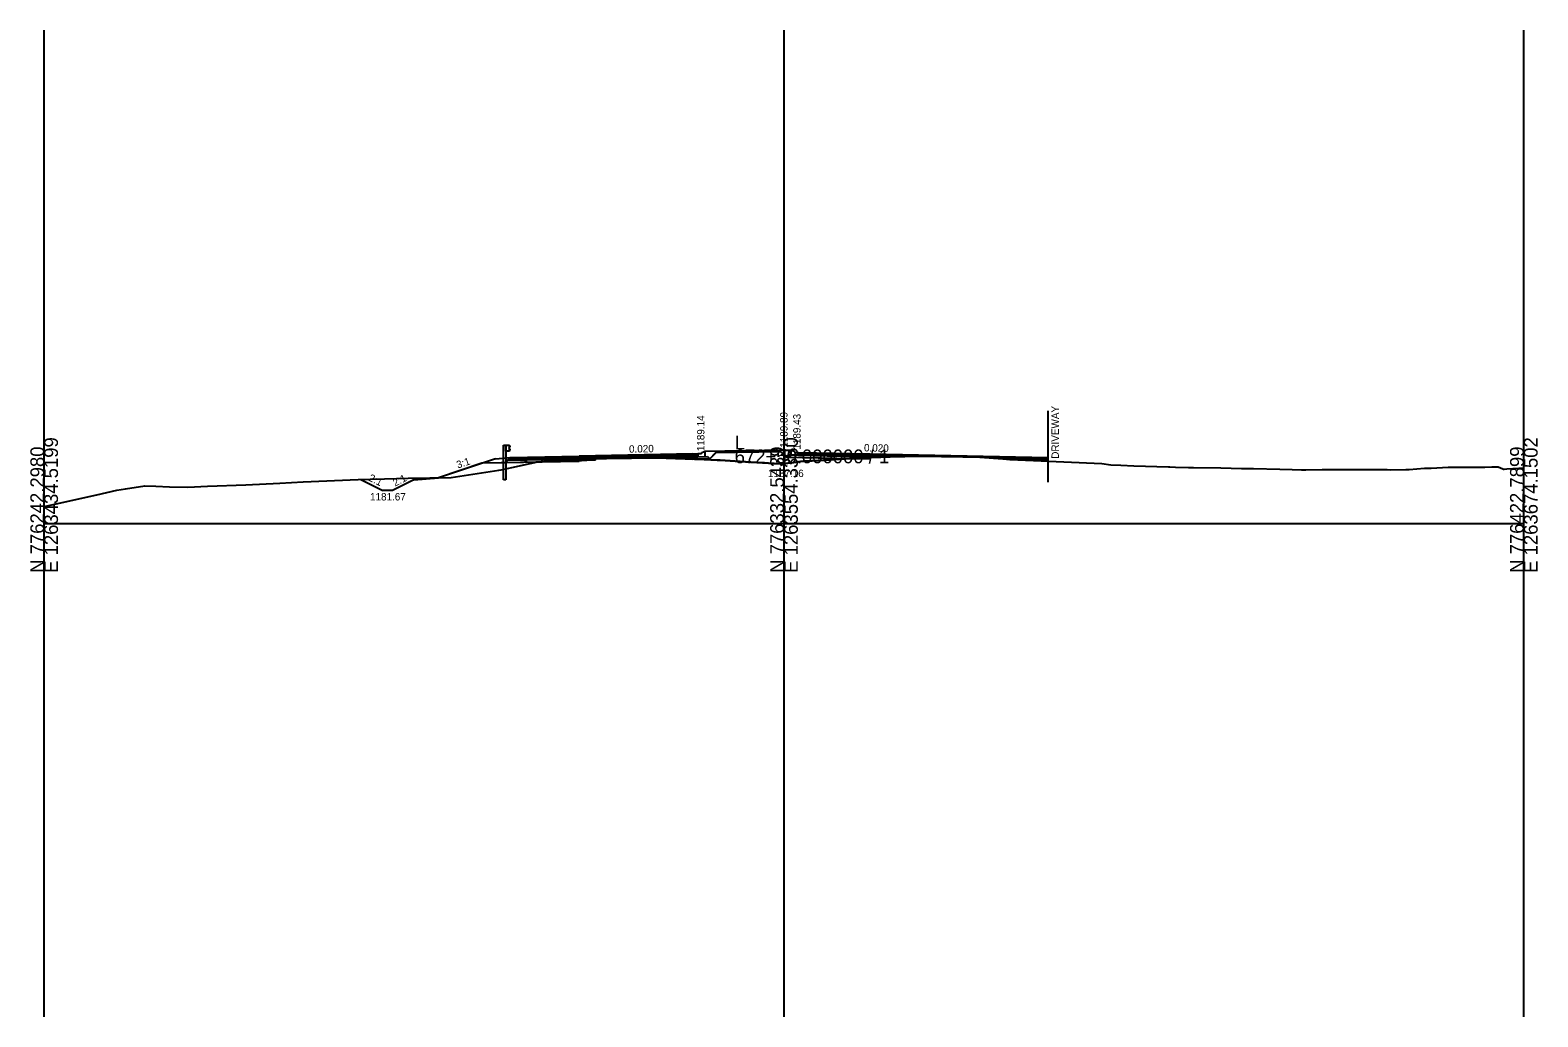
# Model space of a CAD drawing. Extents: x -41 to 1262860, y -100 to 777489.
# Drawn here: x 497.2 to 802.8, y -100 to 100 of the extents above; entities that cross this region are included whole.
import ezdxf

# ---------------------------------------------------------------- set-up
doc = ezdxf.new("R2010")
doc.units = 0
for name, color, linetype in [('Exist Cross Section Cell', 7, 'Continuous'), ('Exist XS Center Line Elevation Label', 7, 'Continuous'), ('Exist XS Ground Line', 7, 'Continuous'), ('Prop CMT Guardrail Graphics', 7, 'Continuous'), ('Prop CMT Pvmt Course 1', 7, 'Continuous'), ('Prop CMT Pvmt Course 4', 7, 'Continuous'), ('Prop CMT Pvmt Surface', 7, 'Continuous'), ('Prop CMT Shear Line', 7, 'Continuous'), ('Prop CMT Shld Paved Course 1', 7, 'Continuous'), ('Prop CMT Shld Paved Course 2', 7, 'Continuous'), ('Prop CMT Shld Paved Course 4', 7, 'Continuous'), ('Prop CMT Subgrade Earthwork', 7, 'Continuous'), ('Prop Conc Curb and Gutter', 7, 'Continuous'), ('Prop Conc Island Cover', 7, 'Continuous'), ('Prop XS Ditch Standard Text', 7, 'Continuous'), ('Prop XS Earthwork Shape', 7, 'Continuous'), ('Prop XS Elevation Labels', 7, 'Continuous'), ('Prop XS Exc Vertical Line 1', 7, 'Continuous'), ('Prop XS Exc Vertical Line 2', 7, 'Continuous'), ('Prop XS Exc Vertical Line 3', 7, 'Continuous'), ('Prop XS Finish Grade', 7, 'Continuous'), ('Prop XS Hydro Elevations', 7, 'Continuous'), ('Prop XS SE Text', 7, 'Continuous'), ('Prop XS Side Slope Text', 7, 'Continuous'), ('Scratch_Level_4', 7, 'Continuous'), ('Scratch_Level_6', 7, 'Continuous')]:
    doc.layers.add(name, color=color, linetype=linetype)

msp = doc.modelspace()

# ---------------------------------------------------------------- linework, layer by layer
at = {"layer": 'Exist Cross Section Cell'}
for p, q in [((650, 0), (650, 15)), ((500, 0), (650, 0)), ((650, 0), (800, 0))]:
    msp.add_line(p, q, dxfattribs=at)
at = {"layer": 'Exist XS Ground Line'}
msp.add_lwpolyline([(500, 3.44), (502.46, 4.01), (510.65, 5.78), (514.74, 6.73), (516.46, 7.06), (520.41, 7.65), (522.67, 7.59), (525.43, 7.43), (529.13, 7.38), (533.11, 7.6), (540.86, 7.86), (547.81, 8.15), (552.5, 8.42), (563.68, 8.92), (566.09, 9.01), (569.03, 9.08), (573.8, 9.17), (582.54, 9.32), (592.15, 10.78), (592.64, 10.85), (596.36, 11.69), (600.09, 12.51), (600.77, 12.59), (603.01, 12.87), (604.8, 12.78), (607.77, 12.72), (611.14, 12.92), (611.74, 12.93), (611.86, 13.16), (613.99, 13.2), (624.15, 13.31), (633.79, 12.96), (636.48, 12.86), (637.06, 12.83), (639.11, 12.7), (643.24, 12.43), (643.28, 12.42), (649.25, 12.08), (651.61, 12.33), (653.33, 12.56), (654.08, 12.62), (654.51, 12.65), (659.36, 12.93), (665.76, 13.31), (671.51, 13.51), (677.56, 13.68), (686.23, 13.51), (689.68, 13.45), (694.38, 13.08), (695.8, 12.96), (700.56, 12.78), (714.47, 12.19), (716.29, 11.91), (718.3, 11.82), (720.92, 11.71), (727.94, 11.47), (728.24, 11.46), (729.37, 11.43), (732.02, 11.38), (733.05, 11.36), (738.59, 11.25), (742.77, 11.17), (745.19, 11.14), (750.54, 11.01), (753.05, 10.96), (754.91, 10.89), (755.83, 10.91), (759.12, 10.92), (759.82, 10.93), (768.32, 10.93), (772.29, 10.92), (773.04, 10.91), (776.09, 10.94), (776.72, 10.97), (779.88, 11.22), (781.19, 11.23), (784.63, 11.4), (784.84, 11.4), (785, 11.4), (785.23, 11.4), (785.56, 11.4), (786.13, 11.4), (792.07, 11.45), (793.49, 11.47), (794.81, 11.48), (795.75, 11.06), (795.89, 11), (796.02, 11.01), (796.54, 11.05), (797.74, 11.15), (797.89, 11.17), (800, 11.25)], dxfattribs=at)
at = {"layer": 'Prop CMT Guardrail Graphics'}
for p, q in [((593.11, 15.87), (593.59, 15.87)), ((593.11, 13.37), (593.11, 15.87)), ((593.59, 14.69), (593.59, 15.87)), ((593.59, 15.87), (594.26, 15.87)), ((593.59, 15.87), (593.59, 13.36)), ((594.26, 15.87), (594.26, 14.69)), ((594.26, 15.79), (594.26, 14.77)), ((594.36, 15.77), (594.26, 15.79)), ((594.27, 15.33), (594.5, 15.53)), ((594.27, 15.24), (594.27, 15.33)), ((594.5, 15.67), (594.36, 15.77)), ((594.5, 15.53), (594.5, 15.67)), ((593.11, 8.86), (593.11, 13.37)), ((594.26, 14.69), (593.59, 14.69)), ((593.59, 13.36), (593.59, 8.86)), ((594.26, 14.77), (594.36, 14.79)), ((594.5, 15.04), (594.27, 15.24)), ((594.36, 14.79), (594.5, 14.89)), ((594.5, 14.89), (594.5, 15.04)), ((593.59, 8.86), (593.11, 8.86))]:
    msp.add_line(p, q, dxfattribs=at)
at = {"layer": 'Prop CMT Pvmt Course 1'}
for p, q in [((631.5, 13.85), (632.5, 13.87)), ((632.5, 13.87), (632.5, 14.12)), ((652.93, 14.41), (652.93, 14.16)), ((652.93, 14.16), (667.5, 13.87))]:
    msp.add_line(p, q, dxfattribs=at)
for points in [[(608.5, 13.64), (608.5, 13.39), (631.5, 13.85), (631.5, 13.85), (631.5, 14.1), (631.5, 14.1), (631.5, 14.1), (608.5, 13.64), (608.5, 13.64)], [(703.5, 13.4), (703.5, 13.15), (703.5, 13.15), (667.5, 13.87), (667.5, 13.87), (667.5, 14.12), (667.5, 14.12), (667.5, 14.12), (703.5, 13.4), (703.5, 13.4), (703.5, 13.4)]]:
    msp.add_lwpolyline(points, dxfattribs=at)
at = {"layer": 'Prop CMT Pvmt Course 4'}
for p in [(593.9, 12.77), (608.5, 12.6)]:
    msp.add_line(p, (593.44, 12.3), dxfattribs=at)
at = {"layer": 'Prop CMT Pvmt Surface'}
for p, q in [((594.5, 13.36), (608.5, 13.64)), ((608.5, 13.64), (631.5, 14.1)), ((631.5, 14.1), (632.5, 14.12)), ((652.93, 14.41), (667.5, 14.12)), ((667.5, 14.12), (703.5, 13.4))]:
    msp.add_line(p, q, dxfattribs=at)
at = {"layer": 'Prop CMT Shear Line'}
msp.add_line((703.5, 22.84), (703.5, 8.4), dxfattribs=at)
at = {"layer": 'Prop CMT Shld Paved Course 1'}
for p, q in [((608.5, 13.39), (594.24, 13.11)), ((594.5, 13.36), (594.24, 13.11)), ((604.5, 13.56), (604.5, 13.56)), ((608.5, 13.64), (608.5, 13.39)), ((608.5, 13.39), (608.5, 13.39))]:
    msp.add_line(p, q, dxfattribs=at)
at = {"layer": 'Prop CMT Shld Paved Course 2'}
for p, q in [((593.9, 12.77), (594.24, 13.11)), ((608.5, 13.06), (593.9, 12.77)), ((603.9, 12.97), (603.9, 12.97)), ((603.9, 12.97), (603.9, 12.97)), ((611.14, 13.45), (608.5, 13.39)), ((608.5, 13.39), (608.5, 13.06)), ((608.5, 13.39), (608.5, 13.39)), ((608.5, 13.39), (608.5, 13.39)), ((608.5, 13.39), (608.5, 13.06)), ((608.5, 13.06), (611.14, 13.11)), ((608.5, 13.06), (608.5, 13.06)), ((608.5, 13.06), (608.5, 13.06)), ((611.74, 13.46), (611.14, 13.45)), ((611.14, 13.45), (611.14, 13.45)), ((611.14, 13.11), (611.74, 13.12)), ((611.14, 13.11), (611.14, 13.11)), ((611.86, 13.46), (611.74, 13.46)), ((611.74, 13.46), (611.74, 13.46)), ((611.74, 13.12), (611.84, 13.13)), ((611.84, 13.13), (611.86, 13.16)), ((611.84, 13.13), (611.84, 13.13)), ((613.99, 13.5), (611.86, 13.46)), ((611.86, 13.16), (613.99, 13.2)), ((624.15, 13.71), (613.99, 13.5)), ((613.99, 13.5), (613.99, 13.5)), ((613.99, 13.2), (617.56, 13.24)), ((613.99, 13.2), (613.99, 13.2)), ((617.56, 13.24), (624.15, 13.37)), ((617.56, 13.24), (617.56, 13.24)), ((617.56, 13.24), (617.56, 13.24)), ((631.5, 13.85), (624.15, 13.71)), ((624.15, 13.71), (624.15, 13.71)), ((624.15, 13.71), (624.15, 13.71)), ((624.15, 13.37), (631.5, 13.52)), ((624.15, 13.37), (624.15, 13.37)), ((624.15, 13.37), (624.15, 13.37)), ((631.5, 13.52), (631.5, 13.85)), ((631.5, 13.85), (631.5, 13.85)), ((631.5, 13.85), (631.5, 13.85)), ((631.5, 13.52), (632.5, 13.54)), ((631.5, 13.52), (631.5, 13.52)), ((632.5, 13.87), (632.5, 13.54)), ((652.93, 13.83), (652.93, 14.16)), ((652.93, 13.83), (667.5, 13.54)), ((667.5, 13.54), (667.5, 13.87)), ((667.5, 13.87), (667.5, 13.87)), ((667.5, 13.87), (671.51, 13.79)), ((670.63, 13.48), (667.5, 13.54)), ((671.51, 13.51), (670.63, 13.48)), ((670.63, 13.48), (670.63, 13.48)), ((671.51, 13.79), (671.51, 13.79)), ((671.51, 13.79), (677.56, 13.67)), ((677.39, 13.67), (671.51, 13.51)), ((671.51, 13.51), (671.51, 13.51)), ((677.56, 13.67), (677.39, 13.67)), ((686.23, 13.5), (677.56, 13.67)), ((677.56, 13.67), (677.56, 13.67)), ((677.56, 13.67), (677.56, 13.67)), ((677.56, 13.67), (686.23, 13.5)), ((689.68, 13.43), (686.23, 13.5)), ((686.23, 13.5), (686.23, 13.5)), ((686.23, 13.5), (686.23, 13.5)), ((686.23, 13.5), (686.23, 13.5)), ((686.23, 13.5), (689.68, 13.43)), ((690.09, 13.42), (689.68, 13.43)), ((689.68, 13.43), (689.68, 13.43)), ((689.68, 13.43), (689.68, 13.43)), ((689.68, 13.43), (689.68, 13.43)), ((689.68, 13.43), (694.38, 13.33)), ((694.38, 13.08), (690.09, 13.42)), ((690.09, 13.42), (690.09, 13.42)), ((690.09, 13.42), (690.09, 13.42)), ((694.38, 13.33), (694.38, 13.33)), ((694.38, 13.33), (694.38, 13.33)), ((694.38, 13.33), (695.8, 13.31)), ((695.63, 12.98), (694.38, 13.08)), ((694.38, 13.08), (694.38, 13.08)), ((694.38, 13.08), (694.38, 13.08)), ((695.8, 12.97), (695.63, 12.98)), ((695.63, 12.98), (695.63, 12.98)), ((695.8, 13.31), (695.8, 13.31)), ((695.8, 13.31), (700.56, 13.21)), ((700.56, 12.88), (695.8, 12.97)), ((695.8, 12.97), (695.8, 12.97)), ((695.8, 12.97), (695.8, 12.97)), ((700.56, 13.21), (703.5, 13.15)), ((700.56, 13.21), (700.56, 13.21)), ((700.56, 13.21), (700.56, 13.21)), ((703.5, 12.82), (700.56, 12.88)), ((700.56, 12.88), (700.56, 12.88)), ((700.56, 12.88), (700.56, 12.88)), ((703.5, 13.15), (703.5, 13.15)), ((703.5, 13.15), (703.5, 13.15)), ((703.5, 13.15), (703.5, 12.82)), ((703.5, 12.82), (703.5, 12.82))]:
    msp.add_line(p, q, dxfattribs=at)
at = {"layer": 'Prop CMT Shld Paved Course 4'}
for p, q in [((597.4, 12.84), (597.9, 12.85)), ((603.9, 12.97), (603.9, 12.97)), ((608.5, 13.06), (608.5, 12.6)), ((611.14, 12.92), (608.5, 12.76)), ((611.74, 12.93), (611.14, 12.92)), ((611.74, 12.93), (611.84, 13.13)), ((617.56, 13.24), (624.15, 13.31)), ((631.5, 13.04), (624.15, 13.31)), ((631.5, 13.06), (631.5, 13.52)), ((631.5, 13.06), (634.95, 13.13)), ((632.5, 13.54), (634.5, 13.58)), ((634.5, 13.58), (634.95, 13.13)), ((650.93, 13.87), (650.48, 13.42)), ((650.48, 13.42), (667.5, 13.08)), ((652.93, 13.83), (650.93, 13.87)), ((667.5, 13.54), (667.5, 13.08)), ((670.63, 13.48), (667.5, 13.37)), ((695.8, 12.96), (695.63, 12.98)), ((695.8, 12.96), (700.56, 12.78)), ((703.5, 12.65), (700.56, 12.78))]:
    msp.add_line(p, q, dxfattribs=at)
at = {"layer": 'Prop CMT Subgrade Earthwork'}
for p, q in [((608.5, 12.6), (588.75, 12.21)), ((608.5, 12.6), (608.5, 12.76)), ((634.95, 13.13), (631.5, 13.06)), ((631.5, 13.06), (631.5, 13.04)), ((634.95, 13.13), (636.44, 14.62)), ((650.48, 13.42), (649.03, 14.87)), ((650.48, 13.42), (667.5, 13.08)), ((667.5, 13.08), (667.5, 13.37))]:
    msp.add_line(p, q, dxfattribs=at)
at = {"layer": 'Prop Conc Curb and Gutter'}
for p, q in [((633.19, 14.14), (632.5, 14.12)), ((632.5, 14.12), (632.5, 13.54)), ((632.5, 13.54), (634, 13.57)), ((633.25, 14.21), (633.25, 14.2)), ((634, 14.57), (633.35, 14.35)), ((634, 13.57), (634, 14.57)), ((634, 13.57), (634, 13.57)), ((651.43, 14.86), (652.08, 14.64)), ((651.43, 13.86), (651.43, 14.86)), ((652.93, 13.83), (651.43, 13.86)), ((652.18, 14.51), (652.18, 14.49)), ((652.24, 14.43), (652.93, 14.41)), ((652.93, 13.83), (652.93, 14.41))]:
    msp.add_line(p, q, dxfattribs=at)
for centre, radius, start, end in [((633.19, 14.2), 0.0625, 271.1458, 360), ((633.4, 14.21), 0.146, 108.435, 180), ((652.03, 14.51), 0.146, 0, 71.565), ((652.24, 14.49), 0.0625, 180, 268.8542)]:
    msp.add_arc(centre, radius, start, end, dxfattribs=at)
at = {"layer": 'Prop Conc Island Cover'}
for p, q in [((650, 14.89), (634, 14.57)), ((634, 14.3), (634, 14.3)), ((650, 14.89), (651.43, 14.86))]:
    msp.add_line(p, q, dxfattribs=at)
at = {"layer": 'Prop XS Earthwork Shape'}
for points in [[(599.71, 12.43), (593.44, 12.3), (588.75, 12.21), (579.96, 9.28), (582.54, 9.32), (592.15, 10.78), (592.64, 10.85), (596.36, 11.69)], [(608.5, 12.6), (599.71, 12.43), (600.09, 12.51), (600.77, 12.59), (603.01, 12.87), (604.8, 12.78), (607.77, 12.72), (608.5, 12.76)], [(636.18, 14.36), (649.27, 14.62), (650.48, 13.42), (663.28, 13.17), (659.36, 12.93), (654.51, 12.65), (654.08, 12.62), (653.33, 12.56), (651.61, 12.33), (649.25, 12.08), (643.28, 12.42), (643.24, 12.43), (639.11, 12.7), (637.06, 12.83), (636.48, 12.86), (633.79, 12.96), (631.5, 13.04), (631.5, 13.06), (634.95, 13.13)], [(667.5, 13.08), (667.5, 13.37), (665.76, 13.31), (663.28, 13.17)]]:
    msp.add_lwpolyline(points, close=True, dxfattribs=at)
at = {"layer": 'Prop XS Exc Vertical Line 1'}
msp.add_line((500, -100), (500, 100), dxfattribs=at)
at = {"layer": 'Prop XS Exc Vertical Line 2'}
msp.add_line((650, -100), (650, 100), dxfattribs=at)
at = {"layer": 'Prop XS Exc Vertical Line 3'}
msp.add_line((800, -100), (800, 100), dxfattribs=at)
at = {"layer": 'Prop XS Finish Grade'}
for p, q in [((591.5, 13.12), (579.96, 9.28)), ((591.5, 13.12), (594.5, 13.36)), ((594.5, 13.36), (593.44, 12.3)), ((574.96, 8.86), (579.96, 9.28)), ((564.17, 8.94), (568.64, 6.7)), ((570.64, 6.7), (568.64, 6.7)), ((574.96, 8.86), (570.64, 6.7))]:
    msp.add_line(p, q, dxfattribs=at)
at = {"layer": 'Scratch_Level_4'}
msp.add_line((800, -100), (800, 100), dxfattribs=at)
at = {"layer": 'Scratch_Level_6'}
msp.add_line((500, -100), (500, 100), dxfattribs=at)

# ---------------------------------------------------------------- texts
at = {"layer": 'Exist Cross Section Cell'}
for s, p in [('N 776242.2980', (500, -10)), ('E 1263434.5199', (502.8, -10)), ('N 776332.5439', (650, -10)), ('E 1263554.3350', (652.8, -10)), ('N 776422.7899', (800, -10)), ('E 1263674.1502', (802.8, -10))]:
    msp.add_text(s, height=2.8, rotation=90, dxfattribs=at).set_placement(p)
for s, p in [('L', (640, 15)), ('672+50.000000 / 1', (640, 12.2))]:
    msp.add_text(s, height=2.8, dxfattribs=at).set_placement(p)
at = {"layer": 'Exist XS Center Line Elevation Label'}
msp.add_text('1187.16', height=1.5, dxfattribs=at).set_placement((646.74, 9.41))
at = {"layer": 'Prop XS Ditch Standard Text'}
msp.add_text('1181.67', height=1.5, dxfattribs=at).set_placement((566.07, 4.67))
at = {"layer": 'Prop XS Elevation Labels'}
for s, p in [('1189.14', (633.87, 14.66)), ('1189.43', (653.36, 14.97))]:
    msp.add_text(s, height=1.5, rotation=90, dxfattribs=at).set_placement(p)
at = {"layer": 'Prop XS Hydro Elevations'}
for s, p in [('1189.89', (650.72, 15.36)), ('DRIVEWAY', (705.73, 13.13))]:
    msp.add_text(s, height=1.5, rotation=90, dxfattribs=at).set_placement(p)
at = {"layer": 'Prop XS SE Text'}
for rotation, p in [(1.1458, (618.59, 14.35)), (358.8542, (666.21, 14.62))]:
    msp.add_text('0.020', height=1.5, rotation=rotation, dxfattribs=at).set_placement(p)
at = {"layer": 'Prop XS Side Slope Text'}
for s, rotation, p in [('3:1', 18.4349, (583.87, 11.13)), ('2:1', 333.6935, (565.62, 8.77)), ('2:1', 26.5651, (571.14, 7.46))]:
    msp.add_text(s, height=1.5, rotation=rotation, dxfattribs=at).set_placement(p)

doc.saveas('drawing.dxf')
